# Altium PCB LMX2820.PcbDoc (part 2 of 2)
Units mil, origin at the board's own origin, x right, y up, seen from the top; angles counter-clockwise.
Board outline 4000 x 4000 mil, 4 copper layers (Top Layer, RF GND, Signal GND, Bottom Layer), stack 61.2 mil thick; 127 components, 75 nets, 393 pads, 472 vias.
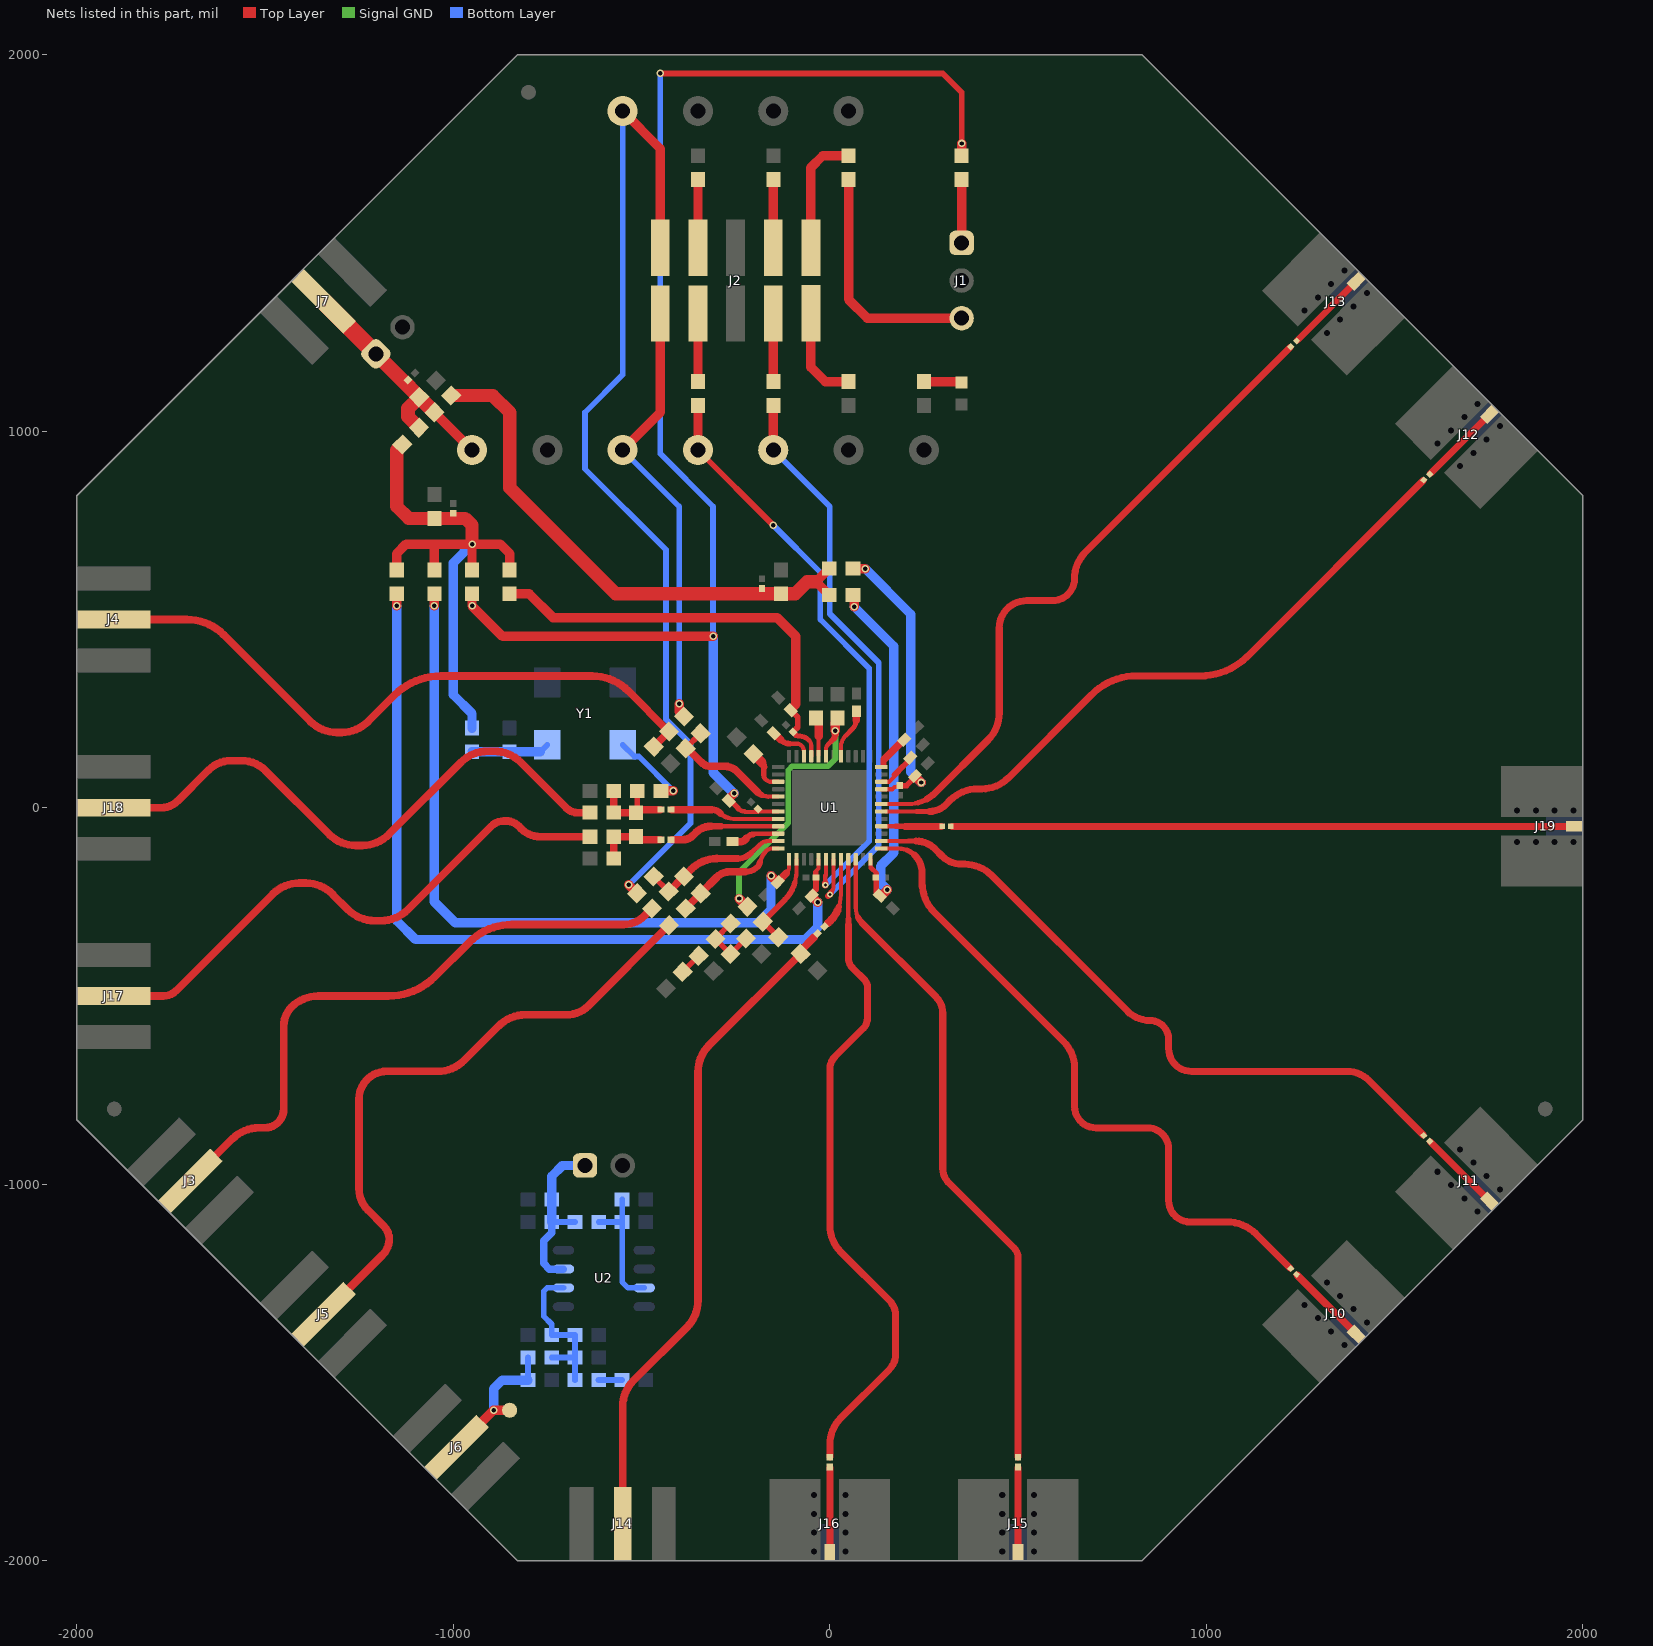
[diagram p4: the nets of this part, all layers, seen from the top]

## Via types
v1: diameter 20, hole 11.81, Top Layer to Bottom Layer, tented both sides, 469 vias
v2: diameter 16, hole 8, Top Layer to Bottom Layer, tented both sides, 3 vias

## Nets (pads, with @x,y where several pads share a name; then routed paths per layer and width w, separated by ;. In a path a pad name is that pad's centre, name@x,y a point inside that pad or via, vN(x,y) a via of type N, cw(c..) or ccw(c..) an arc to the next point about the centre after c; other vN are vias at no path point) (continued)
NetC1_2: C1.2 R19.2 R20.2 U2.3 | length 346.5
  Bottom Layer w15: R19.2@-613.5,-1100 C1.2@-551.49,-1100 ; R20.2@-551.49,-1040 C1.2@-551.49,-1100 ; U2.3@-492.72,-1275 -535.63,-1275 -551.49,-1259.14 C1.2@-551.49,-1100
NetC1LF_1: C1LF.1 C2LF.1 R3LF.2 R28.1 | length 173.4
  Top Layer w10: C2LF.1@-303.73,-348.73 C2LF.1@-303.73,-347.73
  Top Layer w15: C2LF.1@-303.73,-348.73 C1LF.1@-263.73,-388.73 R28.1@-222.27,-347.27 ; C2LF.1@-303.73,-347.73 R3LF.2@-263.27,-307.27
NetC1LFA_2: C1LFA.2 R2LFA.2 R3LFA.1 R16.2 R17.1 U2.6 | length 425.2
  Bottom Layer w15: R3LFA.1@-738.5,-1460 C1LFA.2@-676.5,-1460 ; U2.6@-707.28,-1275 -750.67,-1275 -760,-1284.33 -760,-1350 -738.5,-1371.5 R17.1@-738.5,-1400 R16.2@-676.5,-1400 C1LFA.2@-676.5,-1460 ; R2LFA.2@-676.5,-1520 C1LFA.2@-676.5,-1460
NetC2_1: C2.1 C3.1 J7.1 J8.1 R18.2 R21.1 TP12.1 | length 701.1
  Top Layer w10: -1135.77,1135.81 C2.1@-1120.19,1135.81 -1120.19,1120.23 -1120.19,1120.14
  Top Layer w25: R21.1@-1050.02,1049.98 TP12.1@-950,950
  Top Layer w36: R18.2@-1090.73,1009.27 -1120,1038.54 -1120,1060.5 C3.1@-1090.27,1090.23
  Top Layer w39: J8.1@-1205.36,1205.39 -1135.77,1135.81 -1120.19,1120.23 -1115.77,1115.81 ; -1120.19,1120.14 C3.1@-1090.27,1090.23 R21.1@-1050.02,1049.98
  Top Layer w47: J7.1@-1344.39,1344.89 J8.1@-1205.36,1205.86
  Top Layer w50: J8.1@-1205.36,1205.39 J8.1@-1205.36,1205.86
NetC2LF_2: C2LF.2 R2LF.2 | length 60
  Top Layer w15: R2LF.2@-390.73,-435.73 C2LF.2@-348.27,-393.27
NetC2LFA_2: C2LFA.2 R2LFA.1 | length 62
  Bottom Layer w16: R2LFA.1@-613.5,-1520 C2LFA.2@-551.5,-1520
NetC3LF_1: C3LF.1 R3LF.1 U1.43 | length 742.8
  Top Layer w10: C3LF.1@15,225.23 cw(c33.78,225.23) C3LF.1@20.5,238.5
  Top Layer w11: U1.43@-9.84,145 -9.84,156.44 cw(c5.35,156.44) -5.39,167.18
  Top Layer w13: -5.39,167.18 9.84,182.42
  Top Layer w15: R3LF.1@-219.27,-262.73 R3LF.1@-218.73,-262.73
  Top Layer w16: 9.84,182.42 ccw(c-2.61,194.87) 15,194.87
  Top Layer w20: 15,194.87 v1(15,205)
  Top Layer w25: v1(-241,-241) R3LF.1@-219.27,-262.73 ; v1(15,205) C3LF.1@15,225.23
  Signal GND w15: v1(-241,-241) -241,-171 -110,-40 -110,100 -100,110 -5,110 15,130 v1(15,205)
NetC3LFA_2: C3LFA.2 J6.1 R3LFA.2 TP10.1 | length 399.9
  Top Layer w15: J6.1@-991.14,-1698.14 J6.1@-991.04,-1698.14
  Top Layer w25: J6.1@-991.14,-1698.14 -893,-1600 v1(-892.9,-1600) TP10.1@-850,-1600
  Bottom Layer w15: C3LFA.2@-801.5,-1520 R3LFA.2@-801.5,-1460
  Bottom Layer w25: v1(-892.9,-1600) -892.9,-1542.9 -870,-1520 C3LFA.2@-801.5,-1520
NetC10_1: C10.1 J10.1 | length 221.9
  Top Layer w18.7: C10.1@1241.44,-1241.45 J10.1@1398.34,-1398.34
NetC10_2: C10.2 U1.25 | length 1802.5
  Top Layer w11: U1.25@136.81,-108.27 190,-108.27 ; 183.6,-108.27 184.6,-108.27
  Top Layer w12: 188.58,-108.49 cw(c183.6,-165.4) 224,-125
  Top Layer w14: 204.14,-112.32 cw(c184.6,-166) 225,-125.6
  Top Layer w18.7: 225,-125 cw(c176.72,-173.28) 245,-173.28 245,-198.46 ccw(c357.35,-198.46) 277.91,-277.91 620.71,-620.71 cw(c550,-691.42) 650,-691.42 650,-793.13 ccw(c706.87,-793.13) 706.87,-850 843.03,-850 cw(c843.03,-906.97) 900,-906.97 900,-1043.41 ccw(c956.59,-1043.41) 956.59,-1100 1055.17,-1100 cw(c1055.17,-1208.23) 1131.7,-1131.7 C10.2@1221.85,-1221.86
NetC11_1: C11.1 C12.1 R23.1 U1.33 | length 794.9
  Top Layer w11: U1.33@136.81,49.21 165.97,49.21 172.19,55.44 182.44,55.44 185,57.99 C12.1@186,58.99
  Top Layer w15: C12.1@185,57.99 203,57.99 ; 204,59 227.5,82.5 C11.1@230.3,85.3
  Top Layer w20: C11.1@226.3,84.3 226.3,83.7 C11.1@227.5,82.5
  Top Layer w25: R23.1@61.51,635.03 v1(94,635) ; C11.1@227.5,82.5 v1(243,67)
  Bottom Layer w25: v1(94,635) 215,514 215,95 v1(243,67)
NetC13_2: C13.2 C14.2 R22.1 U1.24 | length 1015.1
  Top Layer w11: 108.27,-159.91 U1.24@108.27,-136.81
  Top Layer w12: C13.2@125,-225 125,-174
  Top Layer w13: 109.77,-159.91 123.01,-173.15 ; C13.2@123,-225 123,-173
  Top Layer w25: R22.1@61.51,565.03 65,561.55 v1(65,534) ; C13.2@138.58,-232.42 v1(153,-218)
  Bottom Layer w25: v1(65,534) 170,429 170,-120 135,-155 135,-200 v1(153,-218)
NetC15_1: C15.1 J11.1 | length 221.9
  Top Layer w16: J11.1@1751.79,-1044.79 J11.1@1751.89,-1044.79
  Top Layer w18.7: C15.1@1594.94,-887.95 J11.1@1751.79,-1044.79
NetC15_2: C15.2 U1.26 | length 1837
  Top Layer w11: U1.26@136.81,-88.58 229.24,-88.58
  Top Layer w12: 185,-88.58 221.68,-88.58
  Top Layer w14: 210,-88.58 234.41,-88.58
  Top Layer w18.7: 229.24,-88.58 cw(c229.24,-159.42) 279.32,-109.32 ; 279.33,-109.33 298.79,-128.79 ccw(c350,-77.57) 350,-150 358.58,-150 cw(c358.58,-250) 429.29,-179.29 790.25,-540.25 ; 790.28,-540.28 ccw(c850,-480.5) 850,-565 cw(c850,-615) 900,-615 900,-640 ccw(c960,-640) 960,-700 1374.29,-700 cw(c1374.29,-778.97) 1430.13,-723.13 C15.2@1575.35,-868.36
NetC16_1: C16.1 J12.1 | length 221.7
  Top Layer w18: C16.1@1595.1,887.99 J12.1@1751.89,1044.79
NetC16_2: C16.2 U1.30 | length 1810.9
  Top Layer w11: U1.30@148.94,-9.84 276.83,-9.84
  Top Layer w14: 230,-9.84 264.7,-9.84
  Top Layer w18.7: 264.7,-9.84 ccw(c264.7,51.63) 308.16,8.16 319.75,19.75 cw(c392.78,-53.29) 392.78,50 403.58,50 ccw(c403.58,150) 474.29,79.29 695.83,300.83 cw(c814.53,182.13) 814.53,350 983.59,350 ccw(c983.59,527.46) 1109.08,401.98 C16.2@1575.51,868.4
NetC17_1: C17.1 C18.1 R27.1 U1.45 | length 1172.7
  Top Layer w10: C17.1@-103.3,259.3 C17.1@-103.3,261.7
  Top Layer w11: -80.07,190.05 cw(c-80.07,156.2) -78.31,190 ; -56.14,180.13 -55.02,179.02 cw(c-69.03,165) -49.21,165 U1.45@-49.21,136.81
  Top Layer w13: -89.59,193.51 ccw(c-81.11,202) -80.07,190.05 ; -78.31,190 cw(c-80.07,156.2) -56.14,180.13
  Top Layer w15: C17.1@-103.3,259.3 -85,241 -85,213.63 C18.1@-97.81,200.81 -90.21,193.21
  Top Layer w25: R27.1@-850,568.5 -798.5,568.5 -735,505 -140,505 -90,455 -90,275 C17.1@-103.3,261.7
NetC19_1: C19.1 C20.2 R26.1 U1.17 | length 2206.7
  Top Layer w11: -37.01,-168.65 -29.53,-161.17 U1.17@-29.53,-136.81
  Top Layer w15: C20.2@-37.01,-185 -37.01,-171.5
  Top Layer w16: C19.1@-48.29,-228.29 -37,-217 ; -37.01,-216 C20.2@-37.01,-185
  Top Layer w20: C19.1@-48.3,-234.7 C19.1@-48.3,-233.3
  Top Layer w25: v1(-1150,536) R26.1@-1150,568.5 ; C19.1@-48.3,-234.7 v1(-32,-251)
  Bottom Layer w25: v1(-1150,536) -1150,-300 -1100,-350 -65,-350 -32,-317 v1(-32,-251)
NetC21_1: C21.1 R25.1 U1.13 | length 1935.8
  Top Layer w11: -114.99,-173.99 ccw(c-131.25,-157.75) -108.27,-157.75 U1.13@-108.27,-136.81
  Top Layer w20: C21.1@-139.7,-197.3 C21.1@-138.3,-197.3 -115,-174
  Top Layer w25: v1(-1050,536) R25.1@-1050,568.5 ; v1(-156,-181) C21.1@-139.7,-197.3
  Bottom Layer w25: v1(-1050,536) -1050,-250 -995,-305 -190,-305 -156,-271 v1(-156,-181)
NetC24_1: C24.1 J13.1 | length 221.7
  Top Layer w18: C24.1@1241.55,1241.55 J13.1@1398.34,1398.34
NetC24_2: C24.2 U1.31 | length 1854.2
  Top Layer w11: U1.31@136.81,9.84 208.42,9.84 ccw(c208.42,109.84) 279.13,39.13
  Top Layer w14: 234.3,13.25 ccw(c208.42,109.84) 279.13,39.13
  Top Layer w18.7: 258.42,23.24 ccw(c208.42,109.84) 279.13,39.13 420.71,180.71 ccw(c350,251.42) 450,251.42 450,477.14 cw(c522.86,477.14) 522.86,550 591.42,550 ccw(c591.42,608.58) 650,608.58 cw(c750,608.58) 679.29,679.29 C24.2@1221.95,1221.95
NetC25_1: C25.1 U1.10 | length 118
  Top Layer w9: U1.10@-136.81,-68.9 U1.10@-136.81,-68.79
  Top Layer w11: -203.28,-68.9 U1.10@-136.81,-68.9
  Top Layer w15: -216.26,-76.72 cw(c-204,-87) -204,-71
  Top Layer w20: C25.1@-259.43,-90 -241.43,-90 ; -238,-90 ccw(c-238,-69.72) -221.39,-81.35
NetC26_1: C26.1 U1.46 | length 114.7
  Top Layer w10: U1.46@-68.9,136.81 U1.46@-68.9,150.27
  Top Layer w11: -105.86,170 -87.07,170 cw(c-87.07,152.93) -75,165 cw(c-89.73,150.27) U1.46@-68.9,150.27
  Top Layer w15: -130,180 ccw(c-105.86,204.14) -105.86,170
  Top Layer w20: C26.1@-148.3,198.3 -130,180
NetC27_2: C27.2 U1.44 | length 142.8
  Top Layer w10: C27.2@-37,238.5 C27.2@-29.53,231.03
  Top Layer w11: U1.44@-29.53,139.8 C27.2@-29.53,231.03
  Top Layer w22: -29.53,190 C27.2@-29.53,231.03
NetC28_2: C28.2 U1.36 | length 125
  Top Layer w10: U1.36@136.81,108.27 U1.36@145,108.27 ; U1.36@140,108.27 140,130 ; U1.36@145.94,108 145.94,127.62 ; C28.2@196.59,180 C28.2@198.3,178.3
  Top Layer w20: 144.94,128.35 C28.2@196.59,180
NetC29_1: C29.1 U1.3 | length 114.6
  Top Layer w11: -170,75 ccw(c-155.27,89.73) -155.27,68.9 U1.3@-136.81,68.9
  Top Layer w13: -175,87.07 ccw(c-157.93,87.07) -170,75
  Top Layer w15: -175,87.07 -175,107.93
  Top Layer w18: -180,120 cw(c-192.07,107.93) -175,107.93
  Top Layer w25: C29.1@-202.73,142.73 -180,120
NetC30_2: C30.2 U1.34 | length 180.6
  Top Layer w9: U1.34@136.81,68.9 U1.34@136.98,69.08
  Top Layer w11: U1.34@136.81,68.9 157.12,68.9 213.3,125.07 C30.2@213.3,133.3 ; 169.65,87.52 C30.2@220.83,138.69
NetC31_1: C31.1 U1.41 | length 136
  Top Layer w11: U1.41@29.53,136.81 29.53,160.57 cw(c72.89,160.57) 42.23,191.23
  Top Layer w13: 42.23,191.23 60.38,209.38 ccw(c37.14,232.63) 70.01,232.63
  Top Layer w15: C31.1@70,256.38 C31.1@70,259.38
  Top Layer w20: 70.01,232.64 C31.1@70,256.38
NetC32_1: C32.1 U1.20 | length 238.6
  Top Layer w6: C32.1@-13.81,-315.81 -4.49,-306
  Top Layer w11: 20.25,-272.63 ccw(c-70.47,-230.56) 29.53,-230.56 U1.20@29.53,-136.81
  Top Layer w16: 0.38,-301.43 ccw(c-70.33,-230.72) 24.6,-262.18
  Top Layer w20.5: -4.49,-306 0.12,-301.47 ; 0.38,-301.43 ccw(c-70.33,-230.72) 20.3,-272.98
NetC32_2: C32.2 J14.1 R31.2 | length 1769.1
  Top Layer w6: -41.92,-343.92 C32.2@-32.19,-334.19
  Top Layer w10: R31.2@-77.27,-387.73 R31.2@-77.27,-379.27
  Top Layer w20.5: J14.1@-550,-1901.67 -550,-1591.42 cw(c-450,-1591.42) -520.71,-1520.71 -379.29,-1379.29 ccw(c-450,-1308.58) -350,-1308.58 -350,-701.88 cw(c-250,-701.88) -320.71,-631.17 R31.2@-77.27,-387.73 ; R31.2@-77.27,-379.27 -41.92,-343.92
NetC33_1: C33.1 U1.9 | length 332.9
  Top Layer w10: -316.89,-49.21 -314.97,-49.21
  Top Layer w11: -314.97,-49.21 U1.9@-136.81,-49.21
  Top Layer w12: -285,-49.21 -276,-49.21
  Top Layer w18: -316.89,-49.21 -288.81,-49.21
  Top Layer w20.5: C33.1@-420,-85 -390,-85 ccw(c-390,-48.58) -364.25,-74.33 -356.21,-66.3 cw(c-314.97,-107.54) -314.97,-49.21
NetC33_2: C33.2 R33.2 R34.1 R35.2 | length 189.5
  Top Layer w16: R34.1@-516.22,-85 R34.1@-516.22,-77
  Top Layer w20.5: R35.2@-573.5,-135 R33.2@-573.5,-77 R34.1@-516.22,-77 ; R34.1@-516.22,-85 C33.2@-450,-85
NetC34_1: C34.1 U1.8 | length 314.4
  Top Layer w10: -255.85,-29.52 ccw(c-254.93,20.07) -254.93,-29.53
  Top Layer w11: -290,-15 ccw(c-254.93,20.07) -255.85,-29.52 ; -255.85,-29.53 U1.8@-136.81,-29.53
  Top Layer w12: -290.18,-15.87 ccw(c-257,21) -269.44,-27.01
  Top Layer w18: -314.14,-5 cw(c-314.14,-39.14) -290,-15
  Top Layer w20.5: C34.1@-420,-5 -314.14,-5
NetC34_2: C34.2 R34.2 R37.2 R38.2 R40.1 | length 237.2
  Top Layer w15: R34.2@-515.5,-13 -511.5,-8.99 -511.5,-5 R38.2@-511.5,45
  Top Layer w20.5: R40.1@-573.5,45 R37.2@-573.5,-13 R34.2@-515.5,-13 ; R34.2@-511.5,-5 C34.2@-450,-5
NetC35_1: C35.1 U1.28 | length 333.2
  Top Layer w11: U1.28@134.03,-49.21 C35.1@296.19,-49.21
  Top Layer w12: 160,-49.21 210,-49.21
  Top Layer w15: 175,-49.21 200,-49.21
  Top Layer w18.7: 200,-49.21 C35.1@296,-49.21
NetC35_2: C35.2 J19.1 | length 1636.5
  Top Layer w18.7: C35.2@324,-49.21 J19.1@1960.46,-49.21
NetC36_1: C36.1 R36.1 Y1.4 | length 207.8
  Bottom Layer w15: Y1.4@-768.82,148.5 Y1.4@-750,167.32
  Bottom Layer w25: R36.1@-950,148.5 C36.1@-850,148.5 Y1.4@-768.82,148.5
NetD1_1: D1.1 R15.1 | length 100.8
  Top Layer w25: R15.1@250,1131.5 348.03,1131.5 D1.1@350,1129.53
NetJ1_1: J1.1 R1.1 | length 168.5
  Top Layer w25: J1.1@350,1500 R1.1@350,1668.5
NetJ1_3: J1.3 R3.1 | length 639.2
  Top Layer w25: R3.1@50,1668.5 50,1350 100,1300 J1.3@350,1300
NetJ2_1: J2.1 R3.2 | length 325.5
  Top Layer w25: J2.1@-50,1487.5 -50,1700 -18.5,1731.5 R3.2@50,1731.5
NetJ2_2: J2.2 R2.1 | length 259.4
  Top Layer w25: J2.2@-50,1313.5 -50,1170 -11.5,1131.5 R2.1@50,1131.5
NetJ2_3: J2.3 R4.1 | length 181
  Top Layer w25: J2.3@-150,1487.5 R4.1@-150,1668.5
NetJ2_4: J2.4 R5.1 | length 181
  Top Layer w25: R5.1@-150,1131.5 J2.4@-150,1312.5
NetJ2_7: J2.7 R6.1 | length 181
  Top Layer w25: J2.7@-350,1487.5 R6.1@-350,1668.5
NetJ2_8: J2.8 R7.1 | length 181
  Top Layer w25: R7.1@-350,1131.5 J2.8@-350,1312.5
NetJ2_9: J2.9 R8.1 TP7.1 | length 2715.5
  Top Layer w20: R8.1@-512.27,-227.27 R8.1@-512.27,-226.73
  Top Layer w25: TP7.1@-550,1850 -450,1750 J2.9@-450,1487.5 ; v1(-534,-205) R8.1@-512.27,-226.73
  Bottom Layer w15: TP7.1@-550,1850 -550,1150 -650,1050 -650,900 -435,685 -435,235 -370,170 -370,-41 v1(-534,-205)
NetJ2_10: J2.10 R9.1 TP8.1 | length 1194.1
  Top Layer w15: R9.1@-387.27,242.27 R9.1@-387.27,257.27
  Top Layer w20: R9.1@-400,255 R9.1@-387.27,242.27
  Top Layer w25: TP8.1@-550,950 -450,1050 J2.10@-450,1312.5 ; R9.1@-400,255 v1(-400,276)
  Bottom Layer w15: TP8.1@-550,950 -400,800 v1(-400,276)
NetJ3_1: J3.1 R10.2 | length 1651.5
  Top Layer w10: -1500,-850 ccw(c-1500,-800) -1499.9,-850
  Top Layer w18.7: -1499.9,-850 ccw(c-1500,-800) -1499.14,-849.99 -1499.9,-850
  Top Layer w20.5: J3.1@-1698.19,-991.09 -1586.4,-879.29 cw(c-1515.68,-950) -1515.68,-850 -1499.9,-850 ; -1499.14,-849.99 ccw(c-1500,-800) -1450,-800 -1450,-579.29 cw(c-1379.29,-579.29) -1429.29,-529.29 cw(c-1358.58,-600) -1358.58,-500 -1172.16,-500 ccw(c-1172.16,-325.8) -1048.98,-448.98 -956.87,-356.87 cw(c-843.71,-470.03) -843.71,-310 -547.61,-310 ccw(c-547.61,-231.28) -491.94,-286.94 R10.2@-472.27,-267.27
NetJ4_1: J4.1 R11.1 R12.2 | length 1750.6
  Top Layer w20.5: J4.1@-1901.67,500 -1708.13,500 cw(c-1708.13,359.67) -1608.9,458.9 -1379.29,229.29 ccw(c-1308.58,300) -1308.58,200 -1296.42,200 ccw(c-1296.42,300) -1225.71,229.29 -1156.3,298.7 cw(c-1032.45,174.85) -1032.45,350 -631.05,350 cw(c-631.05,214.67) -535.36,310.36 R11.1@-427.27,202.27 R12.2@-467.27,162.27
NetJ5_1: J5.1 R14.2 | length 1681.8
  Top Layer w17.6: J5.1@-1344.39,-1344.89 J5.1@-1344.39,-1344.39
  Top Layer w20.5: J5.1@-1344.39,-1344.39 -1187.68,-1187.68 ccw(c-1230.36,-1145) -1170,-1145 ccw(c-1218.28,-1145) -1184.14,-1110.86 -1226.94,-1068.06 cw(c-1171.28,-1012.39) -1250,-1012.39 -1250,-773.43 cw(c-1176.57,-773.43) -1176.57,-700 -1041.42,-700 ccw(c-1041.42,-600) -970.71,-670.71 -879.29,-579.29 cw(c-808.58,-650) -808.58,-550 -700,-550 ccw(c-700,-465.5) -640.25,-525.25 R14.2@-427.27,-312.27
NetJ15_1: J15.1 R30.2 | length 225.5
  Top Layer w18.7: J15.1@500,-1977.5 R30.2@500,-1752
NetJ16_1: J16.1 R32.2 | length 225.5
  Top Layer w18.7: J16.1@0,-1977.5 R32.2@0,-1752
NetJ17_1: J17.1 R33.1 | length 1534.1
  Top Layer w18.7: -865,-35 -861.21,-35 ; R33.1@-638.91,-78 ccw(c-638.91,-74.59) R33.1@-636.5,-77
  Top Layer w20.5: J17.1@-1901.67,-500 -1770,-500 ccw(c-1770,-451.72) -1735.86,-485.86 -1479.29,-229.29 cw(c-1408.58,-300) -1408.58,-200 -1391.42,-200 cw(c-1391.42,-300) -1320.71,-229.29 -1279.29,-270.71 ccw(c-1208.58,-200) -1208.58,-300 -1191.42,-300 ccw(c-1191.42,-200) -1120.71,-270.71 -899.14,-49.14 cw(c-865,-83.28) -865,-35 ; -861.21,-35 cw(c-861.21,-86.21) -825.01,-49.99 -818.57,-56.43 ccw(c-768.91,-6.78) -768.91,-77 R33.1@-636.5,-77
NetJ18_1: J18.1 R37.1 | length 1552.1
  Top Layer w20.5: J18.1@-1901.67,0 -1775,0 ccw(c-1775,60.36) -1732.32,17.68 -1650.08,99.92 cw(c-1589.53,39.37) -1589.53,125 -1562.45,125 cw(c-1562.45,34.59) -1498.52,98.52 -1329.29,-70.71 ccw(c-1258.58,0) -1258.58,-100 -1241.42,-100 ccw(c-1241.42,0) -1170.71,-70.71 -979.29,120.71 cw(c-908.58,50) -908.58,150 -891.42,150 cw(c-891.42,50) -820.71,120.71 -699.02,-0.98 ccw(c-670,28.04) -670,-13 R37.1@-636.5,-13
NetR28_2: R28.2 R29.2 U1.14 | length 308.9
  Top Layer w11: -118,-241.55 ccw(c-188.71,-170.84) -88.71,-170.84 ; -88.58,-172.16 U1.14@-88.58,-136.81
  Top Layer w15: R29.2@-136.73,-343.73 R28.2@-177.73,-302.73 -117.87,-242.87 ; -118.79,-243.71 ccw(c-189.5,-173) -92.91,-198.88
NetR30_1: R30.1 U1.22 | length 1774.6
  Top Layer w11: U1.22@68.9,-136.81 68.9,-265.71 ccw(c124.88,-265.71) 79.52,-298.52 ccw(c124.88,-265.71) 85.29,-305.29
  Top Layer w16: 75,-291 ccw(c125.09,-266.01) 79.52,-298.52 ccw(c125.09,-266.01) 85.51,-305.59
  Top Layer w18.7: 85.51,-305.59 281.89,-501.98 cw(c238.19,-545.69) 300,-545.69 300,-958.58 ccw(c351.72,-958.58) 315.15,-995.15 489.39,-1169.39 cw(c463.79,-1195) 500,-1195 R30.1@500,-1724
NetR32_1: R32.1 U1.21 | length 1775
  Top Layer w11: 49.21,-295 49.21,-275 U1.21@49.21,-136.81
  Top Layer w16: 49.21,-310 49.21,-295
  Top Layer w18.7: R32.1@0,-1724.71 0,-1691.42 cw(c100,-1691.42) 29.29,-1620.71 157.32,-1492.68 ccw(c114.64,-1450) 175,-1450 175,-1350 ccw(c114.64,-1350) 157.32,-1307.32 29.29,-1179.29 cw(c100,-1108.58) 0,-1108.58 0,-695 cw(c48.28,-695) 14.14,-660.86 88.39,-586.61 ccw(c60.36,-558.58) 100,-558.58 100,-475 ccw(c75.86,-475) 92.93,-457.93 60.82,-425.82 cw(c88.86,-397.79) 49.21,-397.79 49.21,-310
NetR38_1: R38.1 Y1.3 | length 217.2
  Top Layer w25: R38.1@-448.5,45 v1(-416,45)
  Bottom Layer w15: Y1.3@-550,167.32 -518.68,136 -507,136 v1(-416,45)
PSYNC: R9.2 R11.2 U1.5 | length 363
  Top Layer w9: R11.2@-382.73,157.73 cw(c-382.73,145.66) R11.2@-374.19,154.19
  Top Layer w11: -162.92,29.54 U1.5@-136.81,29.53
  Top Layer w12: -191.29,41.29 ccw(c-162.92,69.66) -162.92,29.54
  Top Layer w15: R11.2@-382.73,157.73 R9.2@-342.73,197.73
  Top Layer w16: -191.29,41.29 ccw(c-162.92,69.66) -180.7,33.69
  Top Layer w20.5: R11.2@-374.19,154.19 -340,120 ccw(c-315.86,144.14) -315.86,110 -278.79,110 cw(c-278.79,64.64) -246.72,96.72 -191.29,41.29
SCK: R7.2 TP6.1 U1.18 | length 1588.9
  Top Layer w11: -12,-181.95 -9.84,-179.79 ; -9.84,-180 -9.84,-179.79 ; U1.18@-9.84,-136.81 -9.84,-179.79
  Top Layer w13: v2(-12,-205) -12,-181.95 -12,-180
  Top Layer w15: TP6.1@-350,950 v1(-150,750)
  Top Layer w16: v2@-12,-207 v2@-12,-200
  Top Layer w25: TP6.1@-350,950 R7.2@-350,1068.5
  Bottom Layer w15: v1(-150,750) -25,625 -25,500 105,370 105,-88 104.11,-88.89 104.11,-89.25 89.25,-104.11 88.89,-104.11 v2(-12,-205)
SDI: R5.2 TP4.1 U1.19 | length 1575.9
  Top Layer w11: v2(0,-230) ccw(c-23.76,-206.24) 9.84,-206.24 U1.19@9.84,-136.81
  Top Layer w16: v2@-4.49,-233.77 ccw(c-23.76,-206.24) v2@3.77,-225.51
  Top Layer w25: TP4.1@-150,950 R5.2@-150,1068.5
  Bottom Layer w15: TP4.1@-150,950 0,800 0,515 130,385 130,-100 v2(0,-230)
SRREQN: R13.2 R14.1 U1.12 | length 319.2
  Top Layer w10: R14.1@-382.73,-267.73 R14.1@-382.73,-267.27
  Top Layer w11: -168.18,-114.24 cw(c-153.77,-128.65) -153.77,-108.27 U1.12@-136.81,-108.27
  Top Layer w12: -185.76,-148.01 cw(c-123.42,-159) -168.18,-114.24
  Top Layer w16: -223.28,-170 ccw(c-223.28,-125.86) -192.07,-157.07 ccw(c-209.14,-140) -185.37,-144.19
  Top Layer w18.7: -265.69,-170 -223.28,-170
  Top Layer w20.5: R14.1@-382.73,-267.27 R13.2@-342.73,-227.27 -299.44,-183.98 cw(c-265.69,-217.73) -265.69,-170
SRREQP: R8.2 R10.1 R13.1 U1.11 | length 405.5
  Top Layer w9: U1.11@-136.98,-88.4 U1.11@-136.81,-88.58
  Top Layer w10: R10.1@-427.73,-222.73 R10.1@-427.27,-222.73
  Top Layer w11: -209.68,-120.64 ccw(c-240,-76.19) -201.95,-114.24 ; -184.81,-97.1 cw(c-164.25,-117.65) -164.25,-88.58 U1.11@-136.81,-88.58
  Top Layer w12: -209.68,-120.64 -184.81,-97.1
  Top Layer w15: R8.2@-467.73,-182.73 R10.1@-427.73,-222.73
  Top Layer w16: -244.34,-135 ccw(c-244.34,-85.98) -209.68,-120.64
  Top Layer w18.7: -300,-135 -244.34,-135
  Top Layer w20.5: R10.1@-427.27,-222.73 R13.1@-387.27,-182.73 -367.5,-162.96 cw(c-300,-230.46) -300,-135
VCC: C4.1 C5.2 R18.1 R24.2 R25.2 R26.2 R27.2 R36.2 | length 1516.2
  Top Layer w25: R26.2@-1150,631.5 -1150,675 -1125,700 -1050,700 ; R25.2@-1050,631.5 -1050,700 ; R24.2@-950,631.5 v1(-950,700) ; R27.2@-850,631.5 -850,675 -875,700 v1(-950,700) ; -1050,700 v1(-950,700)
  Top Layer w35: R18.1@-1135.27,964.73 -1150,950 -1150,800 -1118.5,768.5 C5.2@-1050,768.5 -968.5,768.5 -950,750 -950,725 v1(-950,700)
  Bottom Layer w25: R36.2@-950,211.5 -950,250 -1000,300 -1000,650 v1(-950,700)
VCCAMP: C6.1 C7.1 J9.1 R19.1 U2.7 | length 461.6
  Bottom Layer w15: C7.1@-738.5,-1100 R19.1@-676.5,-1100
  Bottom Layer w20: C7.1@-738.5,-1100 -738.5,-1128.51 -760,-1150 -760,-1210 -745,-1225 U2.7@-707.28,-1225
  Bottom Layer w25: C7.1@-738.5,-1100 C6.1@-738.5,-1040 -738.5,-978.51 -710,-950 J9.1@-650,-950
VCCBUF: C8.1 C9.2 R21.2 R22.2 R23.2 | length 1416.1
  Top Layer w25: R22.2@-1.48,565.03 -36.48,600.03 R23.2@-1.48,635.03
  Top Layer w35: R21.2@-1005.48,1094.52 -894.52,1094.52 -850,1050 -850,850 -568.5,568.5 C9.2@-130,568.5 -91.5,568.5 -59.97,600.03 -36.48,600.03
VCCDIG: C22.1 C23.2 R1.2 R24.1 U1.7 | length 3875.8
  Top Layer w9: U1.7@-137.15,-9.49 U1.7@-136.81,-9.84
  Top Layer w10: C22.1@-268.3,18.3 cw(c-268.3,-2.25) C22.1@-253.77,12.28 ; -225,-11 C23.2@-190,-11 ; C23.2@-195,-5 C23.2@-189.34,-10.66
  Top Layer w11: C23.2@-194.29,-4.19 C23.2@-190.81,-4.19 ; C23.2@-190,-9.84 U1.7@-136.81,-9.84
  Top Layer w11.5: -200.21,-10.11 C23.2@-194.29,-4.19
  Top Layer w12: -240.85,-3.85 ccw(c-226,11) -226,-10
  Top Layer w15: v1(-450,1950) 300,1950 350,1900 v1(350,1764) ; C22.1@-260,15 -242.72,-2.28
  Top Layer w23: C22.1@-269.3,22.7 v1(-254,38)
  Top Layer w25: R24.1@-950,568.5 v1(-950,536) -869,455 v1(-310,455) ; R1.2@350,1731.5 v1(350,1764)
  Bottom Layer w15: v1(-450,1950) -450,940 -310,800 v1(-310,455)
  Bottom Layer w25: v1(-310,455) -310,93.63 v1(-254,38)
pads on no net: FID1.1 FID2.1 FID3.1 FID4.1 FID5.1 FID6.1 J2.5 SH-J1.0 U2.1 U2.5 U2.8 Y1.1

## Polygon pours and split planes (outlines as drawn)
GND on Top Layer "TOP_LAYER_GND_P074" (solid, remove dead copper, pour order 74): -200,-2000 828.5,-2000 2000,-828.5 2000,828.5 828.5,2000 450,2000 450,850 300,700 300,350 140,190 140,-140 0,-140 0,-400 -50,-450 -50,-550 -200,-700
no net on Top Layer "TOP_LAYER_NONET_P066" (solid, remove dead copper, pour order 66): 254.45,-409.73
no net on Top Layer "Top Layer-No Net 1" (solid, remove dead copper, pour order 56): -1155.8,2368.45
no net on Top Overlay "TOP_LAYER_NONET_P068" (solid, pour order 68): -150,150 -125,150 -150,125
GND on Bottom Layer "BOTTOM_LAYER_GND_P072" (solid, remove dead copper, pour order 72): -2000,-828.5 -828.5,-2000 828.5,-2000 2000,-828.5 2000,828.5 828.5,2000 -828.5,2000 -2000,828.5
GND on RF GND "RF_GND_GND_P080" (solid, remove dead copper, pour order 80): -2000,-828.5 -828.5,-2000 828.5,-2000 2000,-828.5 2000,828.5 828.5,2000 -828.5,2000 -2000,828.5
GND on Signal GND "SIGNAL_GND_GND_P082" (solid, remove dead copper, pour order 82): -2000,-828.5 -828.5,-2000 828.5,-2000 2000,-828.5 2000,828.5 828.5,2000 -828.5,2000 -2000,828.5

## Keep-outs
Keep-Out Layer:
  text ".Layer_Name" at -1906,-3999.49 h60

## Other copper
Top Layer:
  pour cut-out: 95,-295 130,-260 130,-230 80,-230 80,-295
  pour cut-out: 183,-167 220,-130 220,-110 120,-110 120,-167
  text "2000.428" at -1355,285 h30
  text "2000.735" at -1305,-30 h30
  text "2000.568" at -1250,-242.58 h30
  text "2000.388" at -1370,-460.26 h30
  text "2000.968" at -1165,-645.26 h30
  text ".Layer_Name" at -1906,-3999.49 h60
RF GND:
  text ".Layer_Name" at -1906,-4000 h60
Signal GND:
  text ".Layer_Name" at -1906,-4000 h60
Bottom Layer:
  text ".Layer_Name" at -1906,-3999.49 h60

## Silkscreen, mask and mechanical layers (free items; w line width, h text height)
Top Overlay:
  lines w6: 295,1300 270,1300 270,1400 295,1400 ; 405,1400 430,1400 430,1500 405,1500
  lines w7: -225,5 -235,15 -215,35 ; -150,-125 -150,-150 -125,-150 ; 125,-150 150,-150 150,-125 ; 125,150 150,150 150,125 ; 322.44,1040.09 377.56,1040.09 ; 322.44,1044.88 377.56,1044.88
  text "HW" at 445,1450 h30
  text "SW" at 205,1350 h30
  text "-" at -1068.25,1224.5 h30 r45
  text "+" at -1170,1112.99 h30 r45
  text "'.PRJ_Number'.PCB_Rev" at 1040,-230 h108.27
  text "+" at -660,-1050 h30
  text "-" at -560,-1050 h30
  text ".Layer_Name" at -1906,-3999.49 h60
Bottom Overlay:
  circle w20: c-430,-1175 r10
  text ".Layer_Name" at -1906,-3999.49 h60
Top Paste:
  text ".Layer_Name" at -1906,-3999.49 h60
Bottom Paste:
  text ".Layer_Name" at -1906,-3999.49 h60
Top Solder:
  drawing of 159 lines, arcs and shapes, not listed
  text ".Layer_Name" at -1906,-3999.49 h60
  text ".Layer_Name" at -1906,-3999.49 h60
Bottom Solder:
  text ".Layer_Name" at -1906,-3999.49 h60
Drill Guide:
  text ".Layer_Name" at -1906,-3999.49 h60
M1 Board Outline:
  the board outline again, w10
  text ".Layer_Name" at -1906,-3999.49 h60
M2 Board Dimensions:
  rectangle: -2483,-3416 -2358,-3291
  rectangle: -2358,-3541 -1983,-3416
  lines w0.5: 1414.25,1414.25 1767.8,1060.7
  lines w7: -2483,-3416 -1483,-3416 ; -2358,-3541 -2358,-3291 ; -2233,-3541 -2233,-3291 ; -1983,-3541 -1983,-3291 ; -1733,-3541 -1733,-3291 ; -2483,-3541 -1483,-3541 -1483,-3291 -2483,-3291 -2483,-3541
  text ".Layer_Name" at -1906,-3999.49 h60
M3 3D STEP Top:
  lines w1: 1047.87,-1130.37 1047.87,-1118.69 ; 1177.61,-1260.11 1189.29,-1260.11
  text ".Layer_Name" at -1906,-3999.49 h60
M4 3D STEP Bottom:
  text ".Layer_Name" at -1906,-3999.49 h60
M5 Assembly Top:
  circle w10: c-147.7,121.1 r0.42
  lines w6: -432.1,1588.3 -416.4,1588.3 -360.1,1532 ; -295.9,-472.5 -292.4,-472.5 -265.4,-445.5 ; -143.5,-292.1 -85.7,-292.1 -59.1,-318.7 ; 30.7,357.8 30.7,369.2
  lines w10: -2775,-4071.17 3825,-4071.17 ; -2775,-3867.83 3827,-3867.83 ; -2775,-3664.5 -2775,-4274.5 1230,-4274.5 3827,-4274.5 3827,-3664.5 -2774.5,-3664.5 -2774.5,-4274.5 -1199,-4274.5 ; -310,-4274.5 -310,-3664.5 ; 957,-3867.83 957,-3664.5 ; 1797,-3867.83 1797,-3664.5 ; 2419,-4281 2419,-4078.17
  text "All SMA connectors to flush to the edges of the board, no gap allowed. This is especially critical" at -2600,-3050 h60
  text "for:  RFOUTAP, RFOUTAN, RFOUTBP, RFOUTBN, RFIN, SROUTP and SROUTN SMA connectors." at -2600,-3150 h60
  text "Install SMA connectors only per manufacturer's instructions." at -2600,-3250 h60
  text "COMPONENTS MARKED 'DNP' SHOULD NOT BE POPULATED." at -1329.5,-3459.5 h60
  text "ASSEMBLY VARIANT:" at -1330,-3575 h60
  text ".VariantName" at -294,-3575 h60
  text "PCB VIEWED FROM TOP SIDE" at -2711.5,-3796.67 h60
  text "BOARD #:" at -235,-3796.67 h60
  text ".PRJ_Number" at 310.5,-3796.67 h60
  text "REV:" at 1155,-3796.67 h60
  text ".PCB_Rev" at 1446.5,-3796.67 h60
  text "SVN REV:" at 1993,-3796.67 h60
  text ".VersionControl_RevNumber" at 2499,-3796.67 h60
  text "TID #:" at -235,-4000 h60
  text ".TID" at 310.5,-4000 h60
  text "PLOT NAME =" at -2711.5,-4205.34 h60
  text ".plot_File_Name" at -1906,-4205.34 h60
  text "GENERATED    :" at -233,-4205.34 h60
  text ".Print_Date" at 636.5,-4205.34 h60
  text ".Print_Time" at 1365.5,-4205.34 h60
M6 Assembly Bottom:
  lines w10: -2775.5,-3868.33 3826.5,-3868.33 ; -2773.5,-4071.67 3826.5,-4071.67 ; -1367.5,-4281.5 -1367.5,-4078.67 ; -745.5,-3868.33 -745.5,-3665 ; 94.5,-3868.33 94.5,-3665 ; 1361.5,-4275 1361.5,-3665 ; 2250.5,-4275 3826,-4275 3826,-3665 -2775.5,-3665 -2775.5,-4275 -178.5,-4275 3826.5,-4275 3826.5,-3665
  text "COMPONENTS MARKED 'DNP' SHOULD NOT BE POPULATED." at 3619,-3459 h60
  text ".VariantName" at 2575,-3575 h60
  text "ASSEMBLY VARIANT:" at 3614,-3575 h60
  text ".VersionControl_RevNumber" at -1447.5,-3797.17 h60
  text "SVN REV:" at -941.5,-3797.17 h60
  text ".PCB_Rev" at -395,-3797.17 h60
  text "REV:" at -103.5,-3797.17 h60
  text ".PRJ_Number" at 741,-3797.17 h60
  text "BOARD #:" at 1286.5,-3797.17 h60
  text "PCB VIEWED FROM BOTTOM SIDE" at 3763,-3797.17 h60
  text ".TID" at 741,-4000.5 h60
  text "TID #:" at 1286.5,-4000.5 h60
  text "TEXAS INSTRUMENTS" at -1578.5,-4205.84 h60
  text ".Print_Time" at -314,-4205.84 h60
  text ".Print_Date" at 415,-4205.84 h60
  text "GENERATED    :" at 1284.5,-4205.84 h60
  text ".plot_File_Name" at 2957.5,-4205.84 h60
  text "PLOT NAME =" at 3763,-4205.84 h60
M9 Title Sheet:
  lines w10: -2974.5,-2099.5 -2774.5,-2099.5 ; -2974.5,275.5 -2774.5,275.5 ; -2974.5,2650.5 -2774.5,2650.5 ; -474.5,-4474.5 -474.5,-4274.5 ; -474.5,4825.5 -474.5,5025.5 ; 2025.5,-4474.5 2025.5,-4274.5 ; 2025.5,4825.5 2025.5,5025.5 ; 3838,-4274.5 3838,-3664.5 8820.5,-3664.5 ; 4525.5,-4474.5 4525.5,-4274.5 ; 4525.5,4825.5 4525.5,5025.5 ; 7025.5,-4474.5 7025.5,-4274.5 ; 7025.5,4825.5 7025.5,5025.5 ; 8820.5,-4274.5 8820.5,-3664.5 ; 8820.5,-3964.5 11820.5,-3964.5 ; 8820.5,-3364.5 11820.5,-3364.5 ; 8821.5,-2770.5 11821.5,-2770.5 ; 9525.5,-4474.5 9525.5,-4274.5 ; 9525.5,4825.5 9525.5,5025.5 ; 10325.5,-4264.5 10325.5,-3664.5 ; 11820.5,-3664.5 8820.5,-3664.5 ; 11820.5,-3064.5 8820.5,-3064.5 ; 11825.5,-3074.5 11825.5,-4274.5 ; 11825.5,-2270 8821.5,-2270 8820.5,-2270 8820.5,-2770.5 8820.5,-3064.5 ; 11825.5,-2099.5 12025.5,-2099.5 ; 11825.5,275.5 12025.5,275.5 ; 11825.5,2650.5 12025.5,2650.5 ; 8820.5,-3664.5 8820.5,-3064.5 ; 11825.5,-4274.5 11825.5,4825.5 -2774.5,4825.5 -2774.5,-4274.5 11825.5,-4274.5 ; -2974.5,-4474.5 -2974.5,5025.5 12025.5,5025.5 12025.5,-4474.5 -2974.5,-4474.5
  text "1" at -1743.16,4895.5 h70
  text "2" at 752.5,4895.5 h70
  text "3" at 3241.84,4895.5 h70
  text "4" at 5748.51,4895.5 h70
  text "5" at 8247.5,4895.5 h70
  text "6" at 10752.5,4895.5 h70
  text "A" at -2899.5,3752.5 h70
  text "A" at 11900.5,3752.5 h70
  text "B" at -2899.5,1372.5 h70
  text "B" at 11900.5,1372.5 h70
  text "C" at -2899.5,-1002.5 h70
  text "C" at 11900.5,-1002.5 h70
  text "PROJECT TITLE:" at 8860.5,-2863.5 h45
  text "DESIGNED FOR:" at 8860.5,-3164.5 h45
  text ".PRJ_Customer" at 8910.5,-3304.5 h70
  text "D" at -2899.5,-3372.5 h70
  text "D" at 11900.5,-3372.5 h70
  text "FILE NAME:" at 8860.5,-3464.5 h45
  text "Texas Instruments (TI) and/or its licensors do not warrant the accuracy or completeness of this specification" at 3891,-3746.34 h45
  text "ENGINEER:" at 8860.5,-3754.5 h45
  text "LAYOUT BY:" at 10365.5,-3754.5 h45
  text "or any information contained therein. TI and/or its licensors do not warrant that this design will meet" at 3846.01,-3859 h45
  text ".PRJ_Engineer" at 8910.5,-3909.49 h70
  text ".PCB_Layout" at 10416,-3909.49 h70
  text "the specifications, will be suitable for your application or fit for any particular purpose, or will operate in" at 3846.01,-3971.67 h45
  text ".Layer_Name" at -1906,-3999.49 h60
  text "ALTIUM DESIGNER VERSION:" at 10365.5,-4064.5 h45
  text "an implementation. TI and/or its licensors do not warrant that the design is production worthy. You should" at 3846.01,-4084.33 h45
  text "completely validate and test your design implementation to confirm the system functionality for your application." at 3891,-4197 h45
  text ".print_Scale" at 8910.5,-4197.83 h70
  text ".Application_BuildNumber" at 10416,-4197.83 h70
  text "1" at -1743.16,-4404.5 h70
  text "2" at 752.5,-4404.5 h70
  text "3" at 3241.84,-4404.5 h70
  text "4" at 5748.51,-4404.5 h70
  text "5" at 8247.5,-4404.5 h70
  text "6" at 10752.5,-4404.5 h70
M10 Fab Notes:
  text "Copper pads for SMA connectors must extend as far to the board edge as processing allows to" at 2505,-1000 h60
  text "ensure proper circuit performance." at 2505,-1100 h60
  text "18.7mil and 20.5mil width traces on top layer should be controlled 50 ohms +/- 5%." at 2505,-1200 h60
  text ".Layer_Name" at -1906,-3999.49 h60
M11 Gerber Information:
  lines w10: -2775,-4071.17 3825,-4071.17 ; -2775,-3867.83 3827,-3867.83 ; -2775,-3664.5 -2775,-4274.5 1230,-4274.5 3827,-4274.5 3827,-3664.5 -2774.5,-3664.5 -2774.5,-4274.5 -1199,-4274.5 ; -310,-4274.5 -310,-3664.5 ; 957,-3867.83 957,-3664.5 ; 1797,-3867.83 1797,-3664.5 ; 2419,-4281 2419,-4078.17
  text "ALL ARTWORK VIEWED FROM TOP SIDE" at -2711.5,-3796.67 h60
  text "BOARD #:" at -235,-3796.67 h60
  text ".PRJ_Number" at 310.5,-3796.67 h60
  text "REV:" at 1155,-3796.67 h60
  text ".PCB_Rev" at 1446.5,-3796.67 h60
  text "SVN REV:" at 1993,-3796.67 h60
  text ".VersionControl_RevNumber" at 2499,-3796.67 h60
  text "LAYER NAME =" at -2711.5,-3999.49 h60
  text "TID #:" at -235,-4000 h60
  text ".TID" at 310.5,-4000 h60
  text "PLOT NAME =" at -2711.5,-4205.34 h60
  text ".plot_File_Name" at -1906,-4205.34 h60
  text "GENERATED    :" at -233,-4205.34 h60
  text ".Print_Date" at 636.5,-4205.34 h60
  text ".Print_Time" at 1365.5,-4205.34 h60
M12 Stackup:
  drawing of 295 lines, arcs and shapes, not listed
  text "Layer" at 2567.5,1257.5 h60
  text "Name" at 2977.41,1257.5 h60
  text "Material" at 3907.16,1257.5 h60
  text "Thickness" at 4866.89,1257.5 h60
  text "Constant" at 5516.73,1257.5 h60
  text "Board Layer Stack" at 6086.59,1257.5 h60
  text "1" at 2567.5,1137.5 h60
  text "Top Overlay" at 2977.41,1137.5 h60
  text "2" at 2567.5,1017.5 h60
  text "Top Solder" at 2977.41,1017.5 h60
  text "Solder Resist" at 3907.16,1017.5 h60
  text "0.40mil" at 4866.89,1017.5 h60
  text "3.5" at 5516.73,1017.5 h60
  text "3" at 2567.5,897.5 h60
  text "Top Layer" at 2977.41,897.5 h60
  text "Copper" at 3907.16,897.5 h60
  text "1.40mil" at 4866.89,897.5 h60
  text "4" at 2567.5,777.5 h60
  text "Dielectric 1" at 2977.41,777.5 h60
  text "Rogers R04350B" at 3907.16,777.5 h60
  text "10.00mil" at 4866.89,777.5 h60
  text "3.66" at 5516.73,777.5 h60
  text "5" at 2567.5,657.5 h60
  text "RF GND" at 2977.41,657.5 h60
  text "Copper" at 3907.16,657.5 h60
  text "1.40mil" at 4866.89,657.5 h60
  text "6" at 2567.5,537.5 h60
  text "Dielectric 2" at 2977.41,537.5 h60
  text "FR-4" at 3907.16,537.5 h60
  text "22.80mil" at 4866.89,537.5 h60
  text "4.2" at 5516.73,537.5 h60
  text "7" at 2567.5,417.5 h60
  text "Signal GND" at 2977.41,417.5 h60
  text "Copper" at 3907.16,417.5 h60
  text "1.40mil" at 4866.89,417.5 h60
  text "8" at 2567.5,297.5 h60
  text "Dielectric 3" at 2977.41,297.5 h60
  text "FR-4" at 3907.16,297.5 h60
  text "22.80mil" at 4866.89,297.5 h60
  text "4.2" at 5516.73,297.5 h60
  text "9" at 2567.5,177.5 h60
  text "Bottom Layer" at 2977.41,177.5 h60
  text "Copper" at 3907.16,177.5 h60
  text "1.40mil" at 4866.89,177.5 h60
  text "10" at 2567.5,57.5 h60
  text "Bottom Solder" at 2977.41,57.5 h60
  text "Solder Resist" at 3907.16,57.5 h60
  text "0.40mil" at 4866.89,57.5 h60
  text "3.5" at 5516.73,57.5 h60
  text "11" at 2567.5,-62.5 h60
  text "Bottom Overlay" at 2977.41,-62.5 h60
  text ".Layer_Name" at -1906,-3999.49 h60
M13 Component Bodies Top:
  text ".Layer_Name" at -1906,-3999.49 h60
M14 Component Bodies Bottom:
  text ".Layer_Name" at -1906,-3999.49 h60
M15 Courtyards Top:
  text ".Layer_Name" at -1906,-3999.49 h60
M16 Courtyards Bottom:
  text ".Layer_Name" at -1906,-3999.49 h60
Drill Drawing:
  circle w10: c2584.12,-566.72 r27.78
  lines w10: 2556.35,-663.94 2611.9,-663.94 2584.12,-719.5 2556.35,-663.94 ; 2556.35,-455.61 2570.24,-455.61 2570.24,-469.5 2598.01,-469.5 2598.01,-455.61 2611.9,-455.61 2611.9,-427.83 2598.01,-427.83 2598.01,-413.94 2570.24,-413.94 2570.24,-427.83 2556.35,-427.83 2556.35,-455.61 ; 2556.35,-344.5 2584.12,-330.61 2611.9,-344.5 2598.01,-316.72 2611.9,-288.94 2584.12,-302.83 2556.35,-288.94 2570.24,-316.72 2556.35,-344.5
  lines w12: 2506,-757 7874.86,-757 ; 2506,-257 7874.86,-257 ; 2970.4,-882 2970.4,-132 ; 3507.26,-882 3507.26,-132 ; 4633.93,-882 4633.93,-132 ; 5060.82,-882 5060.82,-132 ; 5677.66,-882 5677.66,-132 ; 6930.62,-882 6930.62,-132 ; 2506,-882 7874.86,-882 7874.86,-132 2506,-132 2506,-882
  text "Symbol" at 2581,-219.5 h60
  text "Quantity" at 3007.9,-219.5 h60
  text "Finished Hole Size" at 3544.76,-219.5 h60
  text "Plated" at 4671.43,-219.5 h60
  text "Hole Type" at 5098.32,-219.5 h60
  text "Drill Layer Pair" at 5715.16,-219.5 h60
  text "Hole Tolerance" at 6968.12,-219.5 h60
  text "3" at 3007.9,-344.5 h50
  text "8.00mil (0.203mm)" at 3544.76,-344.5 h50
  text "PTH" at 4671.43,-344.5 h50
  text "Round" at 5098.32,-344.5 h50
  text "Top Layer - Bottom Layer" at 5715.16,-344.5 h50
  text "469" at 3007.9,-469.5 h50
  text "11.81mil (0.300mm)" at 3544.76,-469.5 h50
  text "PTH" at 4671.43,-469.5 h50
  text "Round" at 5098.32,-469.5 h50
  text "Top Layer - Bottom Layer" at 5715.16,-469.5 h50
  text "56" at 3007.9,-594.5 h50
  text "16.00mil (0.406mm)" at 3544.76,-594.5 h50
  text "PTH" at 4671.43,-594.5 h50
  text "Round" at 5098.32,-594.5 h50
  text "Top Layer - Bottom Layer" at 5715.16,-594.5 h50
  text "18" at 3007.9,-719.5 h50
  text "40.00mil (1.016mm)" at 3544.76,-719.5 h50
  text "PTH" at 4671.43,-719.5 h50
  text "Round" at 5098.32,-719.5 h50
  text "Top Layer - Bottom Layer" at 5715.16,-719.5 h50
  text "546 Total" at 3007.9,-844.5 h50
  text ".Layer_Name" at -1906,-3999.49 h60
Mechanical 17:
  text ".Layer_Name" at -1906,-3999.49 h60
Mechanical 18:
  text ".Layer_Name" at -1906,-3999.49 h60
Mechanical 19:
  text "2000.212" at 954.37,825 h30
  text "2000.791" at 1407.5,517.5 h30
  text "2000.64" at 967.98,-781.57 h30
  text "2000.859" at 618.3,-911.3 h30
  text "2000.557" at 85.63,-981.3 h30
  text "2000.019" at 282.94,-1202.58 h30
  text ".Layer_Name" at -1906,-3999.49 h60

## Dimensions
-2000,2000 to -2000,-2000 on M2 Board Dimensions
-2000,-2000 to 2000,-2000 on M2 Board Dimensions
-2483,-3541 to -1483,-3541 on M2 Board Dimensions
